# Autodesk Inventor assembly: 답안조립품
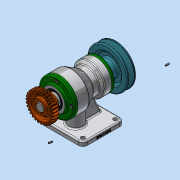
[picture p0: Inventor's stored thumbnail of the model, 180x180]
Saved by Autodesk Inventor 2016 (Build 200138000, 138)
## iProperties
Created: 2019-01
Part Number: 답안조립품
Material: 일반
Document SubType Name: Assembly
Designer: Administrator
Author: Administrator
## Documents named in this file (15)
- C:\Users\Administrator\Desktop\490108V1011\답안조립품.iam
- C:\Users\Administrator\Desktop\490108V1011\본체.ipt
- C:\Users\Administrator\Desktop\490108V1011\멈춤나사 M3.ipt
- C:\Users\Administrator\Desktop\490108V1011\베어링 6205.ipt
- C:\Users\Administrator\Desktop\490108V1011\축.ipt
- C:\Users\Administrator\Desktop\490108V1011\키 6 x 6 x 18.ipt
- C:\Users\Administrator\Desktop\490108V1011\앞커버.ipt
- C:\Users\Administrator\Desktop\490108V1011\오일 실 25 38 8.ipt
- C:\Users\Administrator\Desktop\490108V1011\스퍼기어.ipt
- C:\Users\Administrator\Desktop\490108V1011\뒤커버.ipt
- C:\Users\Administrator\Desktop\490108V1011\베어링 6203.ipt
- C:\Users\Administrator\Desktop\490108V1011\오일 실 17 30 8.ipt
- C:\Users\Administrator\Desktop\490108V1011\V-벨트풀리.ipt
- C:\Users\Administrator\Desktop\490108V1011\키 5 x 5 x 20.ipt
- C:\Users\Administrator\Desktop\490108V1011\볼트 M4.ipt
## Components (1 placed, 1 different names)
1. V-벨트풀리:1
